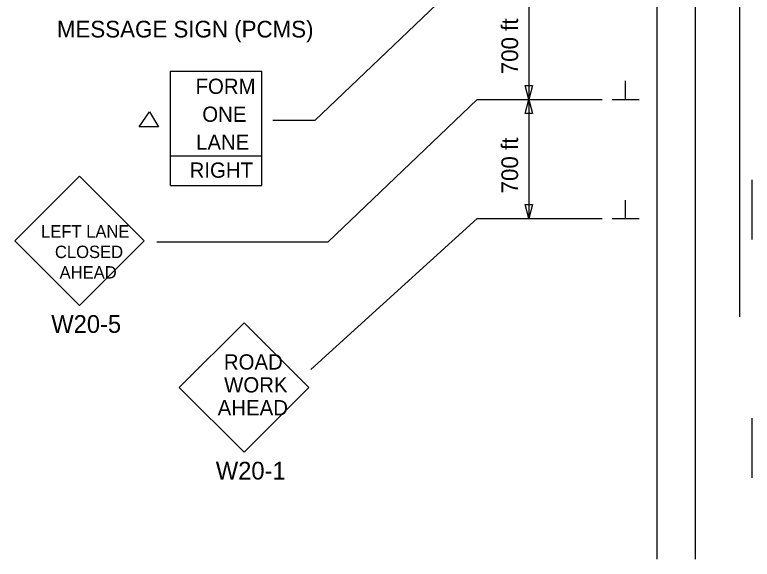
# Model space of a CAD drawing. Extents: x 15277 to 18126, y 1908 to 6555.
# Drawn here: x 16306.9 to 16616.4, y 2305.6 to 2534 of the extents above; entities that cross this region are included whole.
import ezdxf

# ---------------------------------------------------------------- set-up
doc = ezdxf.new("R2010")
doc.units = 0
for name, color, linetype in [('ALI_LEGAL_EX', 7, 'Continuous'), ('PAVT_EDGE_EX', 7, 'Continuous'), ('TRAFFIC_SIGNS_PR', 7, 'Continuous'), ('TYPICAL_TEXT_DIMEN_PR', 7, 'Continuous')]:
    doc.layers.add(name, color=color, linetype=linetype)

msp = doc.modelspace()

# ---------------------------------------------------------------- linework, layer by layer
at = {"layer": 'ALI_LEGAL_EX'}
msp.add_line((16610.98, 3236.46), (16610.98, 2407.28), dxfattribs=at)
for points in [[(16616.35, 2439.74), (16616.35, 2464.74)], [(16616.35, 2339.74), (16616.35, 2364.74)]]:
    msp.add_lwpolyline(points, dxfattribs=at)
at = {"layer": 'PAVT_EDGE_EX'}
for p, q in [((16576.35, 3138.78), (16576.35, 2305.55)), ((16592.35, 3138.78), (16592.35, 2305.55))]:
    msp.add_line(p, q, dxfattribs=at)
at = {"layer": 'TRAFFIC_SIGNS_PR'}
for p, q in [((16372.27, 2462.43), (16372.27, 2510.39)), ((16372.27, 2510.39), (16410.63, 2510.39)), ((16410.63, 2462.43), (16410.63, 2510.39)), ((16372.27, 2474.84), (16410.63, 2474.84)), ((16334.09, 2466.29), (16306.94, 2439.14)), ((16361.24, 2439.14), (16334.09, 2466.29)), ((16372.27, 2462.43), (16410.63, 2462.43)), ((16306.94, 2439.14), (16334.09, 2411.99)), ((16334.09, 2411.99), (16361.24, 2439.14)), ((16403.12, 2404.76), (16375.97, 2377.6)), ((16430.28, 2377.6), (16403.12, 2404.76)), ((16375.97, 2377.6), (16403.12, 2350.45)), ((16403.12, 2350.45), (16430.28, 2377.6))]:
    msp.add_line(p, q, dxfattribs=at)
at = {"layer": 'TYPICAL_TEXT_DIMEN_PR'}
for p, q in [((16494.38, 2548.48), (16432.89, 2489.71)), ((16522.62, 2548.48), (16522.62, 2498.48)), ((16563.23, 2498.48), (16563.23, 2506.26)), ((16522.62, 2498.48), (16521.05, 2504.34)), ((16521.05, 2504.34), (16522.62, 2504.34)), ((16522.62, 2504.34), (16524.2, 2504.34)), ((16524.2, 2504.34), (16522.62, 2498.48)), ((16500.94, 2498.48), (16438.49, 2438.78)), ((16500.94, 2498.48), (16553.35, 2498.48)), ((16521.05, 2492.61), (16522.62, 2498.48)), ((16522.62, 2498.48), (16522.62, 2448.48)), ((16522.62, 2498.48), (16524.2, 2492.61)), ((16557.6, 2498.48), (16568.85, 2498.48)), ((16522.62, 2492.61), (16521.05, 2492.61)), ((16524.2, 2492.61), (16522.62, 2492.61)), ((16432.89, 2489.71), (16415.24, 2489.71)), ((16522.62, 2448.48), (16521.05, 2454.34)), ((16521.05, 2454.34), (16522.62, 2454.34)), ((16522.62, 2454.34), (16524.2, 2454.34)), ((16524.2, 2454.34), (16522.62, 2448.48)), ((16563.23, 2448.48), (16563.23, 2456.26)), ((16500.94, 2448.48), (16431.12, 2385.18)), ((16500.94, 2448.48), (16553.35, 2448.48)), ((16557.6, 2448.48), (16568.85, 2448.48)), ((16366.58, 2438.78), (16438.49, 2438.78))]:
    msp.add_line(p, q, dxfattribs=at)
msp.add_lwpolyline([(16359.17, 2486.96), (16363.53, 2493.26), (16367.24, 2486.96)], close=True, dxfattribs=at)

# ---------------------------------------------------------------- texts
at = {"layer": 'TRAFFIC_SIGNS_PR'}
for s, height, p in [('MESSAGE SIGN (PCMS)', 7, (16324.62, 2524.48)), ('FORM', 6.394, (16382.79, 2500.8)), ('ONE', 6.394, (16385.61, 2489.08)), ('LANE', 6.394, (16383.03, 2477.35)), ('RIGHT', 6.394, (16380.31, 2465.63)), ('LEFT LANE', 5.2, (16317.97, 2440.53)), ('CLOSED', 5.2, (16323.8, 2431.93)), ('AHEAD', 5.2, (16325.75, 2423.33)), ('W20-5', 7.44, (16322.26, 2400.55)), ('ROAD', 6.4, (16394.66, 2385.14)), ('WORK', 6.4, (16394.77, 2375.54)), ('AHEAD', 6.4, (16392.08, 2365.94)), ('W20-1', 7.44, (16391.29, 2339.01))]:
    msp.add_text(s, height=height, dxfattribs=at).set_placement(p)
at = {"layer": 'TYPICAL_TEXT_DIMEN_PR'}
for p in [(16518.1, 2509.05), (16518.1, 2459.05)]:
    msp.add_text('700 ft', height=7, rotation=90, dxfattribs=at).set_placement(p)

doc.saveas('drawing.dxf')
